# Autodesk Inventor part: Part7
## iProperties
Shininess: 64.0
Length Units: 11269
Angle Units: 11279
Time Units: 11290
Mass Units: 11283
Length Display Precision: 3
Angle Display Precision: 2
Compacted: True
Part Number: Part7
Document SubType Name: Modeling
Created: 2002-12
Designer: deepak
Density: 0.0
Volumn: 0.0
Area: 0.0
PropertySet Name: Model Information
Control State: 0
Master: False
Checked Out: False
Author: deepak
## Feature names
1. Extrusion1
